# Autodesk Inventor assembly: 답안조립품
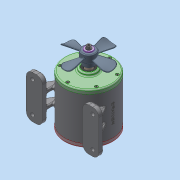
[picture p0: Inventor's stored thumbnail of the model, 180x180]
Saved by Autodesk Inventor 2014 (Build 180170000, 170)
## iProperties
Created: 2024-02
Part Number: 답안조립품
Document SubType Name: Assembly
Designer: dg
Author: dg
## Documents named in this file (20)
- C:\Users\dg\Desktop\640204V1007\답안조립품.iam
- C:\Users\dg\Desktop\640204V1007\본체.ipt
- C:\Users\dg\Desktop\640204V1007\메인 기어 축.ipt
- C:\Users\dg\Desktop\640204V1007\서브 기어 축.ipt
- C:\Users\dg\Desktop\640204V1007\앞커버.ipt
- C:\Users\dg\Desktop\640204V1007\뒷커버.ipt
- C:\Users\dg\Desktop\640204V1007\베어링 608.ipt
- C:\Users\dg\Desktop\640204V1007\오일 실 8 22 7.ipt
- C:\Users\dg\Desktop\640204V1007\오일 실 17 30 8.ipt
- C:\Users\dg\Desktop\640204V1007\베어링 6903.ipt
- C:\Users\dg\Desktop\640204V1007\슬라이더.ipt
- C:\Users\dg\Desktop\640204V1007\스프링.ipt
- C:\Users\dg\Desktop\640204V1007\부시.ipt
- C:\Users\dg\Desktop\640204V1007\키 5 x 5 x 24.ipt
- C:\Users\dg\Desktop\640204V1007\팬날개.ipt
- 팬날개.ipt
- C:\Users\dg\Desktop\640204V1007\스프링 와셔 M6.ipt
- C:\Users\dg\Desktop\640204V1007\육각 소켓 머리 볼트 M6 x 12.ipt
- C:\Users\dg\Desktop\640204V1007\앤드 캡.ipt
- C:\Users\dg\Desktop\640204V1007\육각 소켓 머리 볼트 M4 x 12.ipt
